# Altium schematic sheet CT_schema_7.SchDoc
size 368 x 245 mm
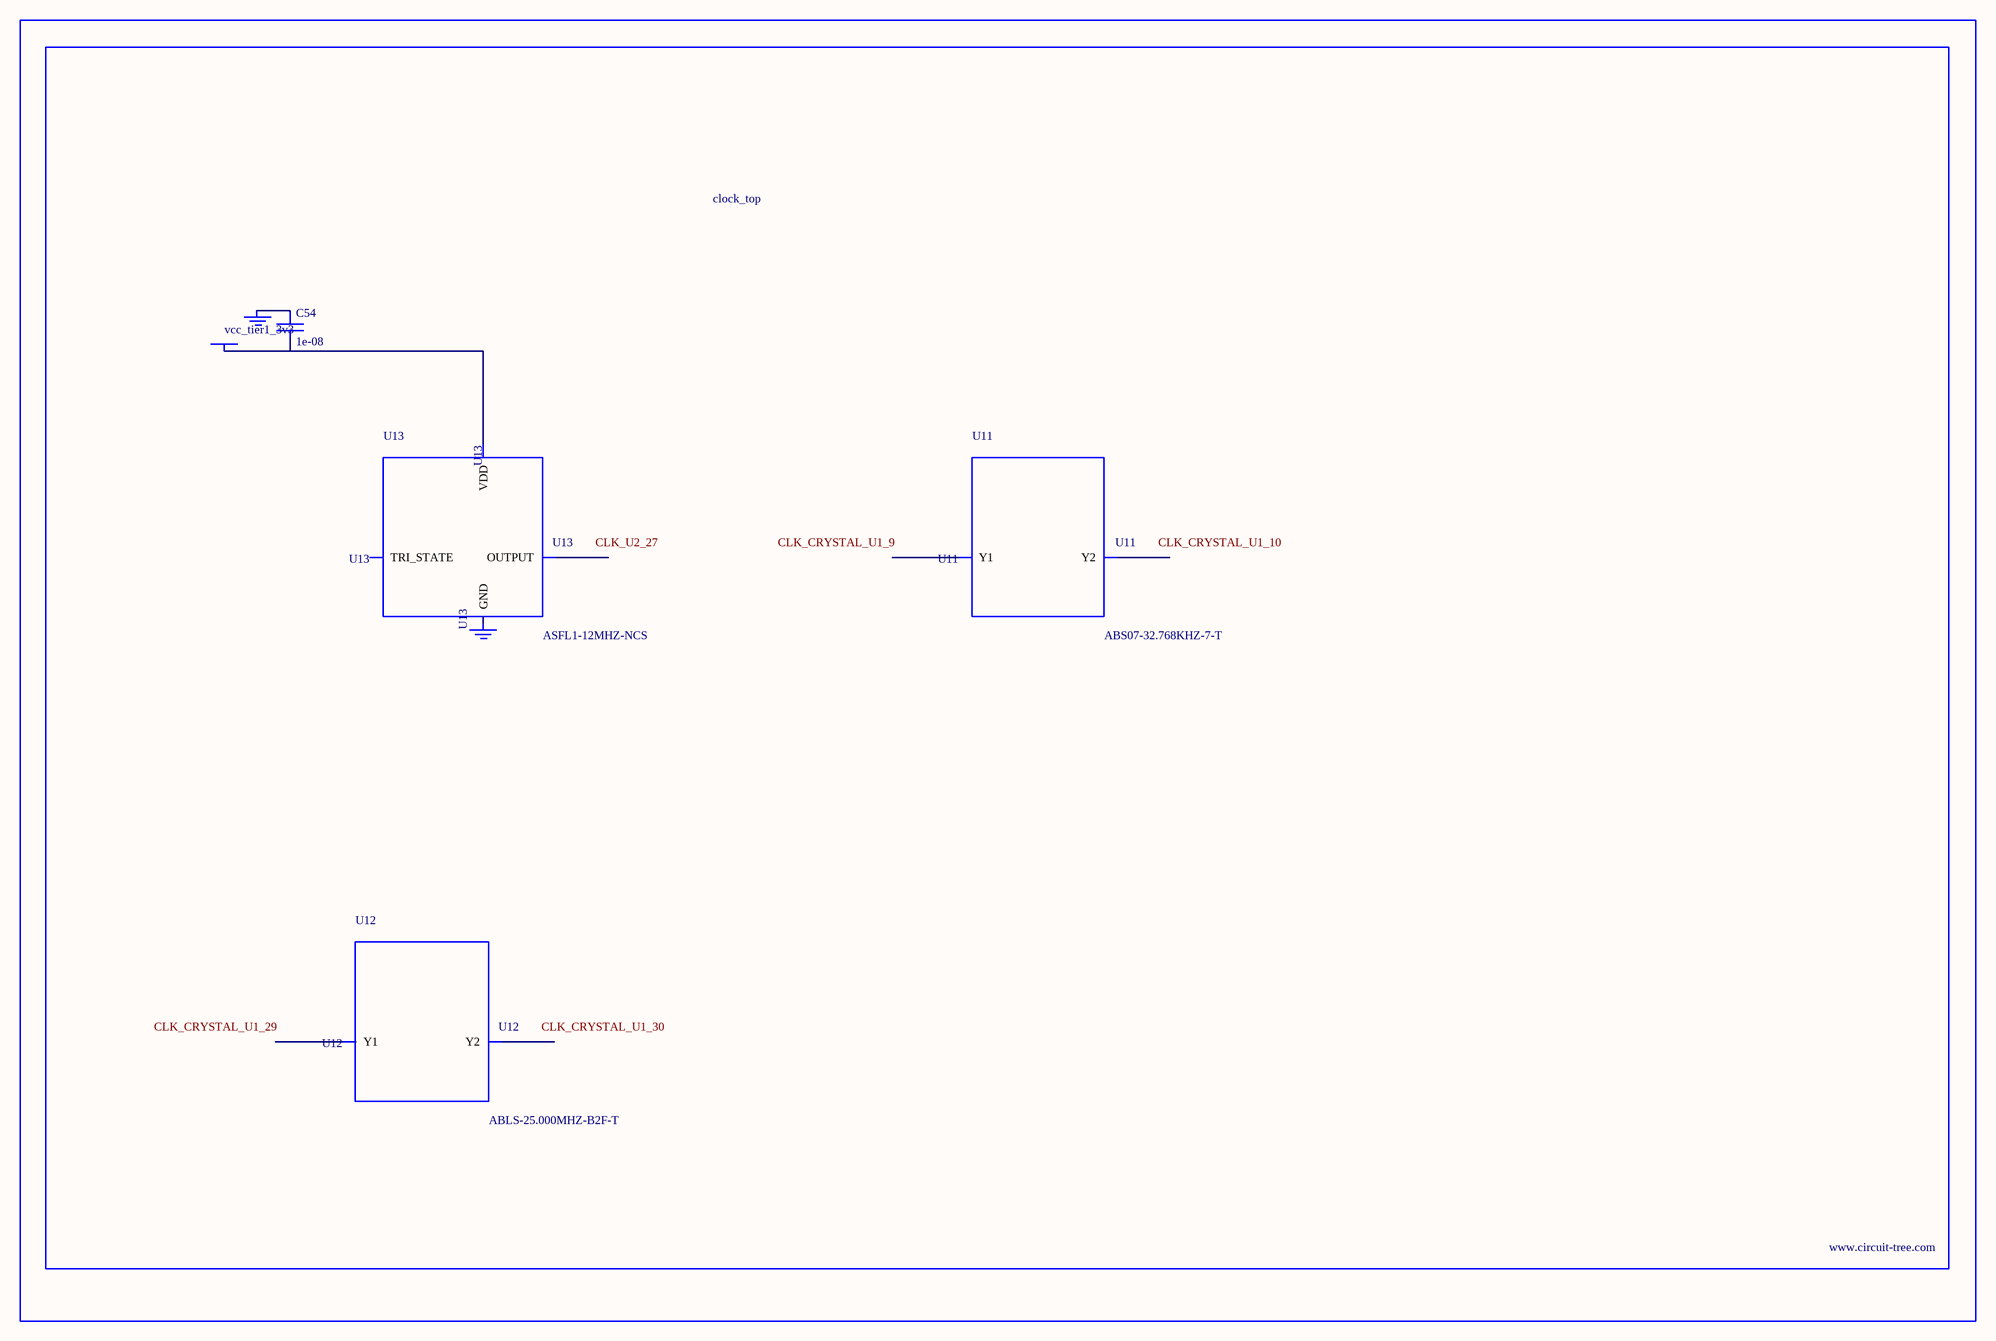
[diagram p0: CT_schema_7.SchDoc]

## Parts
BORDER6  (no value)
C54  1e-08  [C0402]
GND_INSTANCE_6_0  (no value)
GND_INSTANCE_6_1  (no value)
POWER_INSTANCE_6_0  vcc_tier1_3v3
U11  ABS07-32.768KHZ-7-T  [ABS07-32.768KHZ-7-T]
U12  ABLS-25.000MHZ-B2F-T  [ABLS-25.000MHZ-B2F-T]
U13  ASFL1-12MHZ-NCS  [ASFL1]

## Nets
NetC54_1: C54.1 GND_INSTANCE_6_0.0(GND)
NetC54_2: C54.2 POWER_INSTANCE_6_0.0(PWR) U13.4(VDD)

Not connected (* = marked no-connect by the designer): GND_INSTANCE_6_1 0(GND); U11 1(Y1) 2(Y2); U12 1(Y1) 2(Y2); U13 1(TRI_STATE) 2(GND) 3(OUTPUT)

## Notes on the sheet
- Labels drawn without touching a wire or pin: CLK_CRYSTAL_U1_9, CLK_CRYSTAL_U1_10, CLK_CRYSTAL_U1_29, CLK_CRYSTAL_U1_30, CLK_U2_27

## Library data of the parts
BORDER6 = BORDER_PAGE6
C54 = C0402C103K3RAC
GND_INSTANCE_6_0 GND_INSTANCE_6_1 = GND
POWER_INSTANCE_6_0 = PWR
